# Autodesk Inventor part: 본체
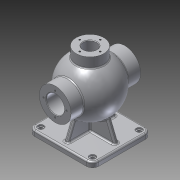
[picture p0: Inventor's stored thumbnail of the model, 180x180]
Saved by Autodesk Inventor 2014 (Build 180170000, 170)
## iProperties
Created: 2015-10
Part Number: 본체
Material: 알루미늄 6061
Document SubType Name: Modeling
Designer: youjin07
Density: 2.71 g/cm^3
Appearance: 알루미늄 - 평지
Mass: 1509.57 g
Surface Area: 1153.7 cm^2
Volume: 557.037 cm^3
Author: youjin07
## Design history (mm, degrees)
sketch "스케치1"
  geometry: L1 (-50.5, -57.5)-(50.5, -57.5); L2 (62.5, -45.5)-(62.5, 45.5); L3 (50.5, 57.5)-(-50.5, 57.5); L4 (-62.5, 45.5)-(-62.5, -45.5); L5 (-62.5, -57.5)-(62.5, 57.5); L6 (62.5, -57.5)-(-62.5, 57.5); C1 r 6 at (-50.5, 45.5); C2 r 6 at (-50.5, -45.5); C3 r 6 at (50.5, -54.613); C4 r 6 at (50.5, 36.387); A1 r 12 centre (-50.5, 45.5) between (-50.5, 57.5) and (-62.5, 45.5); A2 r 12 centre (-50.5, -45.5) between (-62.5, -45.5) and (-50.5, -57.5); A3 r 12 centre (50.5, -45.5) between (50.5, -57.5) and (62.5, -45.5); A4 r 12 centre (50.5, 45.5) between (62.5, 45.5) and (50.5, 57.5); 1 further point
  constraints: 12 end point, 9 tangent, 8 centre point, 8 point on circle, 8 point on line, 3 equal radius, 2 midpoint, 2 parallel, 1 horizontal, 1 perpendicular
  dimensions: "d0" = 125 distance of L6.end L5.end; "d1" = 115 distance of L5.end L6.start; "d2" = 12 radius of A1; "d3" = 12 diameter of C1; "d4" = 12 diameter of C4; "d5" = 12 diameter of C2; "d6" = 12 diameter of C3; "d7" = 101 horizontal distance of C4.centre C1.centre; "d8" = 50.5 horizontal distance of point (0, 0) C1.centre; "d9" = 101 horizontal distance of C3.centre C2.centre; "d10" = 50.5 horizontal distance of C3.centre point (0, 0); "d11" = 91 distance of C2.centre C1.centre; "d12" = 45.5 vertical distance of C1.centre point (0, 0); "d13" = 91 distance of C3.centre C4.centre
extrude "돌출1" new body sketch "스케치1" distance "d14" = 10; taper "d15" = 0 deg
sketch "스케치2"
  geometry: A1 r 12 centre (-50.5, 45.5) between (-50.5, 57.5) and (-62.5, 45.5) reference; A2 r 12 centre (-50.5, -45.5) between (-62.5, -45.5) and (-50.5, -57.5) reference; A3 r 12 centre (50.5, -45.5) between (50.5, -57.5) and (62.5, -45.5) reference; A4 r 12 centre (50.5, 45.5) between (62.5, 45.5) and (50.5, 57.5) reference; 5 further points
  constraints: 4 coincident
  dimensions: "d16" = 101 distance of point (50.5, -45.5) point (-50.5, -45.5) (derived); "d17" = 91 distance of point (-50.5, 45.5) point (-50.5, -45.5) (derived)
hole "구멍1" sketch "스케치2" at (-50.5, -45.5), (-50.5, 45.5), (50.5, 45.5), (50.5, -45.5) diameter "d18" = 8; stored, may be unused: countersink angle "d22" = 90 deg, drill point angle "d24" = 0 deg; dims "d19" = 6, "d20" = 12, "d21" = 3, "d23" = 8
sketch "스케치3"
  geometry: L1 (53, 85)-(-53, 85); A1 r 53 centre (0, 85) between (53, 85) and (-53, 85); 2 further points
  constraints: 2 end point, 2 point on circle, 1 centre point, 1 coincident, 1 horizontal, 1 midpoint, 1 vertical alignment
  dimensions: "d25" = 106 distance of L1.start L1.end; "d26" = 85 distance of point (0, 0) A1.centre
revolve "회전1" sketch "스케치3" stored, may be unused: angle "d27" = 90 deg
node "작업 평면1"
sketch "스케치4"
  geometry: C1 r 31 at (0, 85); 1 further point
  constraints: 1 centre point, 1 vertical alignment
  dimensions: "d29" = 62 diameter of C1; "d30" = 85 distance of point (0, 0) C1.centre
extrude "돌출2" join sketch "스케치4" stored distance "d31" = 10; taper "d32" = 0 deg
node "작업 평면2"
sketch "스케치5"
  geometry: C1 r 31 at (0, 85); 1 further point
  constraints: 1 centre point, 1 vertical alignment
  dimensions: "d34" = 62 diameter of C1; "d35" = 85 distance of point (0, 0) C1.centre
extrude "돌출3" join sketch "스케치5" stored distance "d36" = 10; taper "d37" = 0 deg
node "작업 평면3"
sketch "스케치6"
  geometry: C1 r 27 at (0, 0); 1 further point
  constraints: 1 centre point, 1 coincident
  dimensions: "d39" = 54 diameter of C1
extrude "돌출4" join sketch "스케치6" stored distance "d40" = 10; taper "d41" = 0 deg
sketch "스케치7"
  geometry: L1 (-4, -20.454)-(4, -20.454); L2 (4, -20.454)-(4, 20.454); L3 (4, 20.454)-(-4, 20.454); L4 (-4, 20.454)-(-4, -20.454); L5 (-4, -20.454)-(4, 20.454); L6 (4, -20.454)-(-4, 20.454); 1 further point
  constraints: 12 end point, 2 midpoint, 2 parallel, 1 horizontal, 1 perpendicular
  dimensions: "d42" = 8 distance of L3.end L2.end
extrude "돌출5" join sketch "스케치7" stored distance "d45" = 10; taper "d46" = 0 deg
sketch "스케치8"
  geometry: L1 (-57.5, 0)-(-57.5, 10) reference; L2 (-51.5, 10)-(-39.5, 10) reference; L3 (-45.5, 10)-(-57.5, 10) reference; L4 (45.5, 10)-(-45.5, 10) reference; L5 (-20.454, 10)-(-20.454, 36.27) reference; L6 (39.5, 10)-(51.5, 10) reference; L7 (57.5, 10)-(45.5, 10) reference; L8 (-47.5, 10)-(-33.719, 44.109); L9 (47.5, 10)-(33.719, 44.109); L10 (57.5, 0)-(57.5, 10) reference; A1 r 53 centre (0, 85) between (42.988, 116) and (42.988, 54) reference; 1 further point
  constraints: 4 end point, 2 point on circle, 2 point on line
  dimensions: "d47" = 10 distance from line of L8.start L1; "d48" = 10 distance from line of L9.start L10; "d49" = 22 deg angle of L8 L1; "d50" = 22 deg angle of L9 L10
feature "리브1" dims "d51" = 1, "d52" = 8, "d53" = 0, "d54" = 0, "d55" = 1, "d56" = 1
feature "리브2" dims "d57" = 1, "d58" = 8, "d59" = 0, "d60" = 0, "d61" = 1, "d62" = 1
sketch "스케치9"
  geometry: L1 (-56.5, 10)-(-44.5, 10) reference; L2 (-50.5, 10)-(-62.5, 10) reference; L3 (50.5, 10)-(-50.5, 10) reference; L4 (44.5, 10)-(56.5, 10) reference; L5 (62.5, 10)-(50.5, 10) reference; L6 (-52.5, 10)-(-37.379, 47.426); L7 (52.5, 10)-(37.379, 47.426); L8 (62.5, 0)-(62.5, 10) reference; L9 (-62.5, 0)-(-62.5, 10) reference; A1 r 53 centre (0, 85) between (-27, 130.607) and (27, 130.607) reference; 1 further point
  constraints: 4 end point, 2 point on circle, 2 point on line
  dimensions: "d63" = 10 distance from line of L7.start L8; "d64" = 10 distance from line of L6.start L9; "d65" = 22 deg angle of L6 L9; "d66" = 22 deg angle of L7 L8
feature "리브3" dims "d67" = 1, "d68" = 8, "d69" = 0, "d70" = 0, "d71" = 1, "d72" = 1
feature "리브4" dims "d73" = 1, "d74" = 8, "d75" = 0, "d76" = 0, "d77" = 1, "d78" = 1
sketch "스케치10"
  geometry: L1 (-43, 85)-(43, 85); A1 r 53 centre (0, 85) between (33.719, 44.109) and (-33.719, 44.109) reference; A2 r 43 centre (0, 85) between (43, 85) and (-43, 85); 1 further point
  constraints: 2 end point, 2 point on circle, 1 centre point, 1 coincident, 1 horizontal
  dimensions: "d79" = 43 radius of A2
revolve "회전2" sketch "스케치10" stored, may be unused: angle "d80" = 90 deg
sketch "스케치11"
  geometry: C1 r 31 at (0, 0) reference; C2 r 17.5 at (0, 0); 1 further point
  constraints: 1 centre point, 1 coincident
  dimensions: "d81" = 35 diameter of C2
extrude "돌출6" cut sketch "스케치11" distance "d82" = 26; taper "d83" = 0 deg
sketch "스케치12"
  geometry: C1 r 31 at (0, 0) reference; C2 r 17.5 at (0, 0); 1 further point
  constraints: 1 centre point, 1 coincident
  dimensions: "d84" = 35 diameter of C2
extrude "돌출7" cut sketch "스케치12" distance "d85" = 16; taper "d86" = 0 deg
sketch "스케치13"
  geometry: C1 r 17.5 at (0, 0) reference; C2 r 18.5 at (0, 0); 1 further point
  constraints: 1 centre point, 1 coincident
  dimensions: "d87" = 37 diameter of C2
extrude "돌출8" cut sketch "스케치13" distance "d88" = 1.75; taper "d89" = 0 deg
sketch "스케치14"
  geometry: C1 r 18.5 at (0, 0) reference; C2 r 17.5 at (0, 0); 1 further point
  constraints: 1 centre point, 1 coincident
  dimensions: "d90" = 35 diameter of C2
extrude "돌출9" cut sketch "스케치14" stored distance "d91" = 1.75; taper "d92" = 0 deg
sketch "스케치15"
  geometry: C1 r 27 at (0, 0) reference; C2 r 13 at (0, 0)
  constraints: 1 centre point, 1 coincident
  dimensions: "d93" = 26 diameter of C2
extrude "돌출10" cut sketch "스케치15" stored distance "d94" = 1.75; taper "d95" = 0 deg
sketch "스케치16"
  geometry: C1 r 17.5 at (0, 0) reference; C2 r 31 at (0, 0) reference; A1 r 22.5 centre (0, 0) between (0, 22.5) and (22.5, 0); 3 further points
  constraints: 4 point on circle, 2 horizontal alignment, 2 vertical alignment, 1 centre point, 1 coincident
  dimensions: "d96" = 45 diameter of A1
hole "구멍2" sketch "스케치16" at (0, 22.5), (0, -22.5), (22.5, 0), (-22.5, 0) diameter "d97" = 3.242; stored, may be unused: countersink angle "d101" = 90 deg, drill point angle "d103" = 118 deg; dims "d98" = 12, "d99" = 12, "d100" = 3, "d102" = 15
sketch "스케치17"
  geometry: C1 r 13 at (0, 0) reference; C2 r 27 at (0, 0) reference; A1 r 20 centre (0, 0) between (0, 20) and (20, 0); 2 further points
  constraints: 4 point on circle, 2 horizontal alignment, 2 vertical alignment, 1 centre point, 1 coincident
  dimensions: "d104" = 40 diameter of A1
hole "구멍3" sketch "스케치17" at (0, 20), (20, 0), (0, -20), (-20, 0) diameter "d105" = 3.242; stored, may be unused: countersink angle "d109" = 90 deg, drill point angle "d111" = 118 deg; dims "d106" = 9, "d107" = 4, "d108" = 2, "d110" = 11
sketch "스케치18"
  geometry: C1 r 17.5 at (0, 0) reference; C2 r 31 at (0, 0) reference; A1 r 24 centre (0, 0) between (0, 24) and (24, 0); 3 further points
  constraints: 4 point on circle, 2 horizontal alignment, 2 vertical alignment, 1 centre point, 1 coincident
  dimensions: "d112" = 48 diameter of A1
hole "구멍4" sketch "스케치18" at (0, 24), (24, 0), (0, -24), (-24, 0) diameter "d113" = 3.242; stored, may be unused: countersink angle "d117" = 90 deg, drill point angle "d119" = 118 deg; dims "d114" = 16, "d115" = 4, "d116" = 2, "d118" = 19
node "작업 평면4"
sketch "스케치19"
  geometry: L1 (-27, 150)-(27, 150) reference; L2 (-27, 130.607)-(27, 130.607) reference; L3 (27, 150)-(27, 130.607) reference; L4 (-27, 150)-(-27, 130.607) reference; A1 r 43 centre (0, 85) between (-39.278, 67.5) and (-39.278, 102.5) reference; 2 further points
  constraints: 1 vertical alignment, 1 other
  dimensions: "d121" = 27 distance from line of point (0, 140) L4 (derived); "d122" = 10 distance from line of point (0, 140) L1
feature "엠보싱1" sketch "스케치19" dims "d0" = 125, "d1" = 115, "d2" = 12, "d3" = 12, "d4" = 12, "d5" = 12, "d6" = 12, "d7" = 101, "d8" = 50.5, "d9" = 101, "d10" = 50.5, "d11" = 91, "d12" = 45.5, "d13" = 91, "d123" = 0.5, "d124" = 0
chamfer "모따기1" distance "d125" = 1; stored, may be unused: second distance "d126" = 2, angle "d127" = 45 deg
fillet "모깎기1" dims "d128" = 3
node "솔리드1"
other parameters: "d28" = -68, "d33" = 68, "d120" = -27.5
